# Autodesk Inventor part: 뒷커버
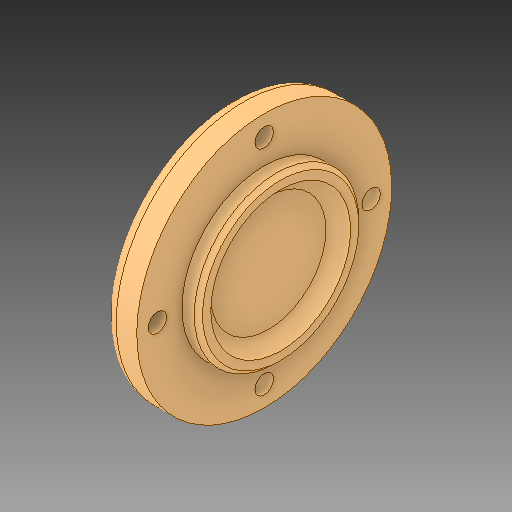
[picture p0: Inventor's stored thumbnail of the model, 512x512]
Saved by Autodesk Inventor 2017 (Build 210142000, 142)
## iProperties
Created: 2024-09
Part Number: 뒷커버
Material: 일반
Document SubType Name: Modeling
Designer: MRC
Density: 1 g/cm^3
Appearance: 기본값
Author: jhkim
Sending System: Autodesk Inventor 2025
Preprocessor: ST-DEVELOPER v20
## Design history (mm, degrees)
feature "솔리드1"
node "솔리드2"
